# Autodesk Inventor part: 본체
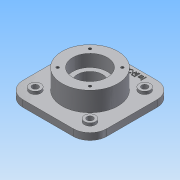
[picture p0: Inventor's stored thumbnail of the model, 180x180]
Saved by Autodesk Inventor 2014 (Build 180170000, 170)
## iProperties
Created: 2015-09
Part Number: 본체
Material: 알루미늄 6061
Document SubType Name: Modeling
Designer: study
Density: 2.71 g/cm^3
Appearance: 알루미늄 - 평지
Author: study
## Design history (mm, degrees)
sketch "스케치1"
  geometry: L1 (45, -75)-(-45, -75); L2 (-75, -45)-(-75, 45); L3 (-45, 75)-(45, 75); L4 (75, 45)-(75, -45); L5 (75, -75)-(-75, 75); L6 (-75, -75)-(75, 75); A1 r 30 centre (-45, 45) between (-45, 75) and (-75, 45); A2 r 30 centre (45, 45) between (75, 45) and (45, 75); A3 r 30 centre (45, -45) between (45, -75) and (75, -45); A4 r 30 centre (-45, -45) between (-75, -45) and (-45, -75); 3 further points
  constraints: 12 end point, 8 point on circle, 8 point on line, 8 tangent, 4 centre point, 3 equal radius, 3 midpoint, 2 parallel, 2 perpendicular, 1 coincident, 1 horizontal
  dimensions: "d0" = 150 distance of L5.end L6.end; "d3" = 30 radius of A1
extrude "돌출1" new body sketch "스케치1" distance "d1" = 12; taper "d2" = 0 deg
sketch "스케치2"
  geometry: L1 (49, -49)-(-49, -49); L2 (-49, -49)-(-49, 49); L3 (-49, 49)-(49, 49); L4 (49, 49)-(49, -49); L5 (49, -49)-(-49, 49); L6 (-49, -49)-(49, 49); C1 r 10 at (-49, 49); C2 r 10 at (49, 49); C3 r 10 at (-49, -49); C4 r 10 at (49, -49); 3 further points
  constraints: 12 end point, 5 coincident, 4 centre point, 3 equal radius, 3 midpoint, 2 parallel, 1 horizontal, 1 perpendicular
  dimensions: "d4" = 98 distance of L2.end L3.end; "d5" = 98 distance of L3.end L1.start; "d6" = 20 diameter of C1
extrude "돌출2" join sketch "스케치2" distance "d7" = 5; taper "d8" = 0 deg
sketch "스케치3"
  geometry: C1 r 10 at (0, 0) reference; C2 r 10 at (0, -98) reference; C3 r 10 at (98, -98) reference; C4 r 10 at (98, 0) reference; 1 further point
hole "구멍1" sketch "스케치3" at (0, -98), (0, 0), (98, 0), (98, -98) diameter "d9" = 11; stored, may be unused: countersink angle "d13" = 90 deg, drill point angle "d15" = 118 deg; dims "d10" = 6, "d11" = 4, "d12" = 2, "d14" = 8
node "작업 평면1"
sketch "스케치5"
  geometry: C1 r 50 at (0, 0); 1 further point
  constraints: 1 centre point, 1 coincident
  dimensions: "d17" = 100 diameter of C1
extrude "돌출3" join sketch "스케치5" distance "d18" = 70; taper "d19" = 0 deg
hole "구멍2" diameter "d22" = 45; stored, may be unused: countersink angle "d26" = 90 deg, drill point angle "d28" = 118 deg; dims "d20" = 10, "d21" = 10, "d23" = 6, "d24" = 62, "d25" = 22, "d27" = 8
sketch "스케치6"
  geometry: L1 (28.991, -28.991)-(-28.991, -28.991); L2 (-28.991, -28.991)-(-28.991, 28.991); L3 (-28.991, 28.991)-(28.991, 28.991); L4 (28.991, 28.991)-(28.991, -28.991); L5 (28.991, -28.991)-(-28.991, 28.991); L6 (-28.991, -28.991)-(28.991, 28.991); C1 r 50 at (0, 0) reference; 4 further points
  constraints: 12 end point, 4 coincident, 2 midpoint, 2 parallel, 2 perpendicular, 1 horizontal
  dimensions: "d30" = 82 distance of L1.end L3.end
hole "구멍3" sketch "스케치6" at (-28.991, 28.991), (-28.991, -28.991), (28.991, -28.991), (28.991, 28.991) diameter "d31" = 4.917; stored, may be unused: countersink angle "d35" = 90 deg, drill point angle "d37" = 118 deg; dims "d32" = 10, "d33" = 62, "d34" = 22, "d36" = 13
node "작업 평면2"
sketch "스케치7"
  geometry: C1 r 50 at (0, 0) reference; 1 further point
  constraints: 1 vertical alignment, 1 other
  dimensions: "d38" = 65 distance of point (0, 65) C1.centre
feature "엠보싱1" sketch "스케치7" dims "d39" = 1, "d40" = 0
node "솔리드1"
mirror "대칭1"
node "투영된 루프1"
node "투영된 루프2"
node "투영된 루프3"
other parameters: "d16" = 23
